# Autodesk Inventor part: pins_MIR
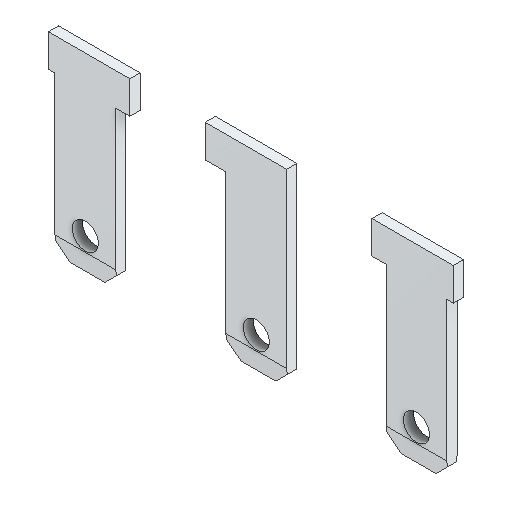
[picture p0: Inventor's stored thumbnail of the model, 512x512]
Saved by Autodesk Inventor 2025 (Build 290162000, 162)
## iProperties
Created: 2025-10
Part Number: pins_MIR
Material: Generico
Document SubType Name: Modeling
Designer: Ryzen5700u
Density: 1 g/cm^3
Appearance: Default
Author: Ryzen5700u
Revision Number: ANY
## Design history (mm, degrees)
derived "pins.ipt"
feature "Solido1::pins.ipt"
feature "Solido2::pins.ipt"
feature "Solido3::pins.ipt"
tag "Lavorazione contrassegno1"
node "Solido1"
node "Solido2"
node "Solido3"
